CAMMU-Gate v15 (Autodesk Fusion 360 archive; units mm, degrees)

design "CAMMU-Gate" references "MR63ZZ", "Slider T-Nut for 2020 - M5"
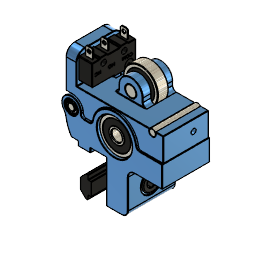
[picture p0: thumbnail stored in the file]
description: Part Number
part number: CAMMU-Linear-Rail-Lead-Screw
part number: Endstop Limit Switch v1
part number: Screw
part number: Brass body
part number: Brass NUT
part number: 625Z_1
named bodies: "Gate bottom (NEW)", "Gate top (NEW)", "3x3x22 pin", "5x5x15 shaft", "3x3x21.5 pin", "Slider-Nut-Spacer-12mm", "Magnet 3x3x10", "Magnet 3x3x10 (1)"

design "MR63ZZ"
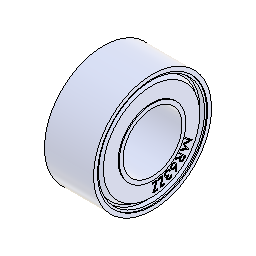
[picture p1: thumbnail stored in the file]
description: STEP AP214
part number: MR63ZZ
description: Part Number
part number: outer shell - mz63zz
part number: inner shell - mz63zz
part number: 1mm ball bearing sphere
part number: MR63ZZ - seal
base_feature "Base Feature1"
base_feature "Base Feature1"
base_feature "Base Feature1"
base_feature "Base Feature1"
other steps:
create_component "CreateComponent1"
create_component "CreateComponent2"
create_component "CreateComponent3"
create_component "CreateComponent4"

design "Slider T-Nut for 2020 - M5"
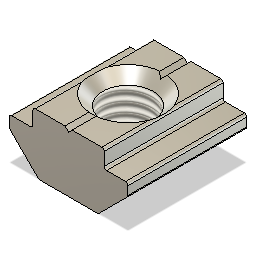
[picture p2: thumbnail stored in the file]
sketch "Sketch1"
  dimension "d1" = 10
  dimension "d4" = 5
  dimension "d5" = 45
  dimension "d6" = 1
  dimension "d7" = 5
  dimension "d8" = 6
  dimension "d9" = 2
  dimension "d10" = 2
  dimension "d12" = 45
  dimension "d13" = 0.3
  dimension "d14" = 5
  dimension "d15" = 1.5
  dimension "d16" = 0.2
extrude "Extrude1" new body sketch "Sketch1" blind 10
hole "Hole1" HoleDepth 5.834 HoleDiameter 4.234 TipAngle 180 CSDiameter 6 CSAngle 90 RefDim1 5 RefDim2 5
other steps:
thread "Thread1"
